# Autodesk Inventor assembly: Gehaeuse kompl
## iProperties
Created: 2006-11
Part Number: Gehaeuse kompl
Cost Center: 4,408 kg
Document SubType Name: Assembly
Designer: Schmidt
Authority: 561836 mm^3
Mass: 6868.97 g
Surface Area: 2361.45 cm^2
Volume: 874.65 cm^3
Density: 7.85339 g/cm^3
SaveDate: 2006-11-06
SaveTime: 22:19
TotalMass: 4,408 kg
TotalVolume: 561836 mm^3
Author: Schmidt
